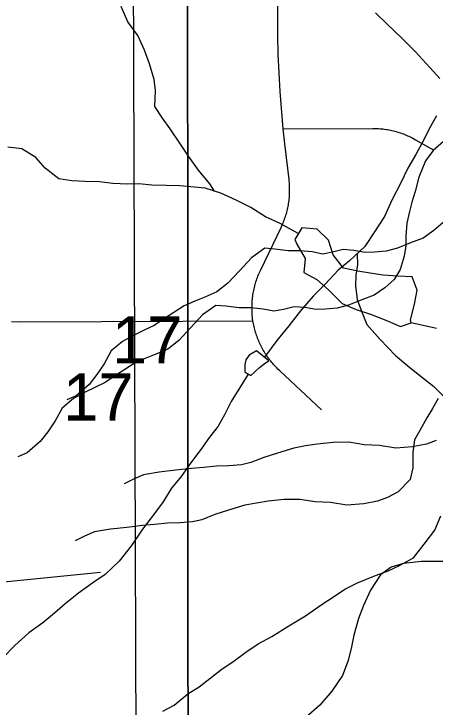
# Model space of a CAD drawing. Extents: x -21.1 to 50.3, y 0 to 22.1.
# Drawn here: x 4.341 to 4.714, y 16.136 to 16.75 of the extents above; entities that cross this region are included whole.
import ezdxf

# ---------------------------------------------------------------- set-up
doc = ezdxf.new("R2010")
doc.units = 0
for name, color, linetype in [('GM_X_Major_River', 7, 'Continuous'), ('GM_X_Minor_Lake', 7, 'Continuous'), ('GM_X_Minor_River', 7, 'Continuous'), ('GM_X_Section', 7, 'Continuous'), ('GM_X_Section_Text', 7, 'Continuous'), ('GM_X_Township_Road', 7, 'Continuous')]:
    doc.layers.add(name, color=color, linetype=linetype)

msp = doc.modelspace()

# ---------------------------------------------------------------- linework, layer by layer
at = {"layer": 'GM_X_Major_River'}
msp.add_lwpolyline([(4.66074, 16.75058), (4.67068, 16.7408), (4.68406, 16.728), (4.69592, 16.71633), (4.70893, 16.70202), (4.71774, 16.69222)], dxfattribs=at)
at = {"layer": 'GM_X_Minor_Lake'}
for points in [[(4.69226, 16.4762), (4.69187, 16.47889), (4.69527, 16.49258), (4.69753, 16.50513), (4.69333, 16.51691), (4.68039, 16.51728), (4.66746, 16.5184), (4.65794, 16.51991), (4.645, 16.52179), (4.63244, 16.52444), (4.62329, 16.53621), (4.61909, 16.54914), (4.60918, 16.55901), (4.59548, 16.56014), (4.58941, 16.54986)], [(4.69225, 16.47623), (4.69187, 16.47889), (4.69527, 16.49258), (4.69753, 16.50513), (4.69333, 16.51691), (4.68039, 16.51728), (4.66746, 16.5184), (4.65794, 16.51991), (4.645, 16.52179), (4.63244, 16.52444), (4.62329, 16.53621), (4.61909, 16.54914), (4.60918, 16.55901), (4.59548, 16.56014), (4.58941, 16.54986)], [(4.58941, 16.54986), (4.59132, 16.54568), (4.59857, 16.53314), (4.59744, 16.5206), (4.60887, 16.51453), (4.61915, 16.50541), (4.63135, 16.49326), (4.64353, 16.48795), (4.65647, 16.48379), (4.6698, 16.47848), (4.68275, 16.47279), (4.69226, 16.4762)], [(4.58941, 16.54986), (4.59132, 16.54568), (4.59857, 16.53314), (4.59744, 16.5206), (4.60887, 16.51453), (4.61915, 16.50541), (4.63135, 16.49326), (4.64353, 16.48795), (4.65647, 16.48379), (4.6698, 16.47848), (4.68275, 16.47279), (4.69225, 16.4762)], [(4.55555, 16.45138), (4.54907, 16.44763), (4.54601, 16.44347), (4.54522, 16.4393), (4.54518, 16.43248), (4.55047, 16.42941), (4.55811, 16.43657), (4.56344, 16.44071), (4.56649, 16.44259)], [(4.56649, 16.44259), (4.55555, 16.45138)]]:
    msp.add_lwpolyline(points, dxfattribs=at)
at = {"layer": 'GM_X_Minor_River'}
for points in [[(4.51842, 16.59266), (4.51438, 16.5992), (4.50409, 16.61135), (4.49532, 16.6235), (4.48769, 16.63528), (4.4793, 16.64782), (4.47243, 16.65731), (4.46557, 16.66757), (4.46631, 16.68164), (4.46515, 16.69152), (4.46095, 16.70521), (4.45636, 16.71737), (4.45064, 16.73028), (4.44187, 16.74244), (4.43576, 16.75612)], [(4.71478, 16.65946), (4.70825, 16.64773), (4.70325, 16.63752), (4.69634, 16.62504), (4.68943, 16.61294), (4.68289, 16.59933), (4.67558, 16.58533), (4.66865, 16.5702), (4.65984, 16.5566), (4.6514, 16.54375), (4.63766, 16.53093), (4.62774, 16.52265), (4.61665, 16.51057), (4.60558, 16.49964), (4.59449, 16.48681), (4.58415, 16.47359), (4.57344, 16.46038), (4.56267, 16.44566)], [(4.72086, 16.63664), (4.71177, 16.62861), (4.70497, 16.61945), (4.69896, 16.60499), (4.69599, 16.59243), (4.69299, 16.58292), (4.69076, 16.57455), (4.68853, 16.56428), (4.68745, 16.55288), (4.6875, 16.54414), (4.68603, 16.53501), (4.68267, 16.52322), (4.67739, 16.51445), (4.66906, 16.50719), (4.65958, 16.50068), (4.64856, 16.49644), (4.63679, 16.49181), (4.62691, 16.4891), (4.61664, 16.48828), (4.60827, 16.48786), (4.59836, 16.4897), (4.58884, 16.49041), (4.57933, 16.48807), (4.57097, 16.48651), (4.56144, 16.48836), (4.55078, 16.48944), (4.54012, 16.48938), (4.52831, 16.49083), (4.51955, 16.49154), (4.5078, 16.48312), (4.49721, 16.47166), (4.48699, 16.46059), (4.47714, 16.45294), (4.46651, 16.44832), (4.45777, 16.44485), (4.44828, 16.44062), (4.43918, 16.43487), (4.43083, 16.42951), (4.42173, 16.42338), (4.413, 16.41915), (4.40275, 16.41415), (4.39365, 16.40917), (4.3838, 16.40075), (4.37739, 16.38932), (4.37097, 16.37979), (4.36417, 16.37101), (4.35281, 16.36107), (4.34445, 16.35761)], [(4.5925, 16.55516), (4.57645, 16.56391), (4.5635, 16.56998), (4.55055, 16.57833), (4.53761, 16.58478), (4.5239, 16.59084), (4.5102, 16.59539), (4.50068, 16.59614), (4.48775, 16.59726), (4.47557, 16.59763), (4.46301, 16.59799), (4.4516, 16.59912), (4.44132, 16.59872), (4.42839, 16.59947), (4.41659, 16.60097), (4.40403, 16.60134), (4.39224, 16.6017), (4.38082, 16.60359), (4.36863, 16.61308), (4.36024, 16.62258), (4.34806, 16.63016), (4.3355, 16.63167)], [(4.72068, 16.56497), (4.71235, 16.55771), (4.70287, 16.5512), (4.69185, 16.54695), (4.68008, 16.54233), (4.6702, 16.53962), (4.65993, 16.5388), (4.65155, 16.53837), (4.64165, 16.54022), (4.63213, 16.54092), (4.62262, 16.53859), (4.61426, 16.53702), (4.60473, 16.53887), (4.59407, 16.53995), (4.58341, 16.53989), (4.5716, 16.54135), (4.56284, 16.54206), (4.55109, 16.53363), (4.5405, 16.52218), (4.53028, 16.51111), (4.52043, 16.50345), (4.5098, 16.49884), (4.50106, 16.49537), (4.49157, 16.49114), (4.48247, 16.48539), (4.47412, 16.48002), (4.46502, 16.47389), (4.45629, 16.46967), (4.44604, 16.46467), (4.43693, 16.45968), (4.42708, 16.45127), (4.42068, 16.43984), (4.41426, 16.4303), (4.40746, 16.42153), (4.39609, 16.41159), (4.38774, 16.40812)], [(4.64441, 16.53722), (4.64485, 16.52785), (4.64327, 16.51838), (4.64321, 16.50889), (4.64464, 16.49674), (4.64837, 16.48647), (4.65323, 16.47468), (4.6649, 16.46133), (4.67847, 16.44721), (4.68942, 16.43804), (4.69999, 16.42963), (4.71245, 16.41969), (4.72413, 16.40785)], [(4.7146, 16.47123), (4.69225, 16.47623)], [(4.54806, 16.4308), (4.53324, 16.40637), (4.52709, 16.39465), (4.52172, 16.38482), (4.51406, 16.375), (4.5064, 16.36404), (4.49721, 16.35196), (4.48879, 16.34025), (4.48037, 16.32968), (4.47232, 16.31683), (4.46236, 16.30361), (4.45471, 16.29341), (4.44512, 16.27906), (4.43403, 16.26509), (4.42181, 16.2534), (4.41075, 16.24588), (4.39817, 16.23685), (4.38635, 16.22744), (4.3768, 16.21915), (4.3665, 16.21049), (4.3543, 16.20183), (4.34171, 16.19053), (4.33139, 16.17997)], [(4.71605, 16.40906), (4.71115, 16.4003), (4.70625, 16.39191), (4.69984, 16.38086), (4.69532, 16.37248), (4.69386, 16.36145), (4.69393, 16.34778), (4.69133, 16.33751), (4.68073, 16.32643), (4.67124, 16.32144), (4.66251, 16.31835), (4.65034, 16.316), (4.6355, 16.31478), (4.62102, 16.31698), (4.60732, 16.31767), (4.59398, 16.31987), (4.5799, 16.31979), (4.56582, 16.31819), (4.55556, 16.31662), (4.54529, 16.31466), (4.53085, 16.3104), (4.51869, 16.30653), (4.5073, 16.30191), (4.49893, 16.29997), (4.4879, 16.29915), (4.47686, 16.2987), (4.46545, 16.2975), (4.4548, 16.29668), (4.44072, 16.29508), (4.42627, 16.29348), (4.4122, 16.29113), (4.40347, 16.28728), (4.39512, 16.28305)], [(4.71453, 16.37196), (4.70579, 16.36887), (4.69363, 16.36652), (4.67879, 16.3653), (4.66431, 16.3675), (4.65061, 16.36818), (4.63727, 16.37039), (4.62319, 16.37031), (4.60911, 16.36871), (4.59885, 16.36713), (4.58858, 16.36518), (4.57414, 16.36092), (4.56198, 16.35705), (4.55059, 16.35243), (4.54222, 16.35048), (4.53119, 16.34966), (4.52015, 16.34922), (4.50874, 16.34802), (4.49809, 16.3472), (4.48401, 16.3456), (4.46956, 16.344), (4.45549, 16.34164), (4.44676, 16.3378), (4.4384, 16.33357)], [(4.47284, 16.13245), (4.4828, 16.13762), (4.49473, 16.14769), (4.5047, 16.154), (4.51431, 16.16145), (4.52508, 16.17003), (4.53467, 16.17596), (4.5462, 16.18452), (4.55695, 16.19195), (4.5692, 16.19861), (4.58416, 16.20788), (4.59874, 16.21677), (4.61371, 16.22718), (4.62368, 16.23349), (4.63367, 16.24055), (4.64477, 16.24608), (4.65929, 16.25194), (4.6719, 16.25669), (4.68147, 16.2611), (4.69449, 16.26812), (4.70379, 16.28013), (4.7131, 16.29253), (4.71862, 16.30536)], [(4.72282, 16.26483), (4.71143, 16.2649), (4.70156, 16.26496), (4.68561, 16.26316), (4.67459, 16.25981), (4.66505, 16.25304), (4.65624, 16.23944), (4.65008, 16.22582), (4.64583, 16.21446), (4.64156, 16.19969), (4.63959, 16.18946), (4.63647, 16.17733), (4.63145, 16.16409), (4.62225, 16.15011), (4.61155, 16.13765), (4.59934, 16.1271)]]:
    msp.add_lwpolyline(points, dxfattribs=at)
at = {"layer": 'GM_X_Section'}
for points in [[(4.44556, 17.13365), (5.45266, 17.13084), (5.44952, 16.13321), (4.44906, 16.1053)], [(5.52017, 16.94387), (5.53343, 15.91957), (5.47621, 15.91802), (4.49511, 15.90479), (4.49436, 16.90218), (4.49435, 16.93023)], [(4.49436, 16.90218), (4.49511, 15.90479), (3.50758, 15.88397), (3.48674, 15.88357), (3.4856, 16.89423)]]:
    msp.add_lwpolyline(points, close=True, dxfattribs=at)
at = {"layer": 'GM_X_Township_Road'}
for points in [[(4.61306, 16.3992), (4.57623, 16.43362), (4.5745, 16.43524), (4.57356, 16.43617), (4.57264, 16.43712), (4.57173, 16.43808), (4.57084, 16.43906), (4.56996, 16.44005), (4.56911, 16.44106), (4.56827, 16.44209), (4.56744, 16.44312), (4.56664, 16.44417), (4.56586, 16.44524), (4.56509, 16.44632), (4.56435, 16.44741), (4.56362, 16.44852), (4.56291, 16.44963), (4.56222, 16.45077), (4.56155, 16.45191), (4.56091, 16.45306), (4.56028, 16.45423), (4.55967, 16.4554), (4.55908, 16.45659), (4.55851, 16.45778), (4.55797, 16.45899), (4.55745, 16.4602), (4.55694, 16.46143), (4.55646, 16.46266), (4.556, 16.4639), (4.55556, 16.46515), (4.55515, 16.46641), (4.55475, 16.46767), (4.55438, 16.46894), (4.55403, 16.47021), (4.5537, 16.4715), (4.55339, 16.47279), (4.55311, 16.47408), (4.55285, 16.47538), (4.55262, 16.47668), (4.55239, 16.47801), (4.55213, 16.47986), (4.55197, 16.48118), (4.55184, 16.48249), (4.55172, 16.48381), (4.55164, 16.48513), (4.55157, 16.48645), (4.55165, 16.49439), (4.55175, 16.49571), (4.55187, 16.49703), (4.552, 16.49834), (4.55217, 16.49965), (4.55236, 16.50097), (4.55256, 16.50227), (4.5528, 16.50358), (4.55305, 16.50487), (4.55333, 16.50617), (4.55363, 16.50745), (4.55395, 16.50874), (4.55429, 16.51002), (4.55466, 16.51129), (4.55505, 16.51255), (4.55546, 16.51381), (4.5559, 16.51506), (4.55635, 16.5163), (4.55683, 16.51754), (4.55733, 16.51876), (4.55784, 16.51998), (4.55838, 16.52119), (4.55895, 16.52239), (4.57755, 16.5612), (4.57829, 16.5628), (4.57882, 16.56401), (4.57933, 16.56523), (4.57982, 16.56646), (4.58029, 16.56769), (4.58073, 16.56894), (4.58116, 16.57019), (4.58156, 16.57145), (4.58194, 16.57272), (4.5823, 16.574), (4.58264, 16.57528), (4.58295, 16.57656), (4.58324, 16.57785), (4.58351, 16.57915), (4.58375, 16.58045), (4.58397, 16.58176), (4.58417, 16.58306), (4.58435, 16.58438), (4.58451, 16.58569), (4.58464, 16.58701), (4.58474, 16.58832), (4.58483, 16.58965), (4.58468, 16.60022), (4.58456, 16.60154), (4.58441, 16.60286), (4.58063, 16.63447), (4.57916, 16.64791), (4.57639, 16.68077), (4.57543, 16.69728), (4.57476, 16.71381), (4.57438, 16.73035), (4.57428, 16.74689), (4.57461, 16.85156)], [(4.57916, 16.64791), (4.65827, 16.64821), (4.66356, 16.64804), (4.66488, 16.64794), (4.6662, 16.64783), (4.66751, 16.64768), (4.66883, 16.64751), (4.67014, 16.64732), (4.67144, 16.64711), (4.67275, 16.64687), (4.67404, 16.64662), (4.67534, 16.64633), (4.67662, 16.64602), (4.6779, 16.6457), (4.67918, 16.64535), (4.68045, 16.64498), (4.68171, 16.64459), (4.68297, 16.64417), (4.68422, 16.64373), (4.68546, 16.64328), (4.6867, 16.64279), (4.68792, 16.64229), (4.68914, 16.64177), (4.69034, 16.64123), (4.69154, 16.64066), (4.69272, 16.64007), (4.6939, 16.63947), (4.6962, 16.6382), (4.71241, 16.62884)], [(4.33892, 16.47738), (4.34638, 16.47699), (4.49046, 16.47758), (4.55239, 16.47801)], [(4.2402, 15.94866), (4.23934, 16.16261), (4.23974, 16.17595), (4.24042, 16.18176), (4.24145, 16.18689), (4.2435, 16.19441), (4.24647, 16.20102), (4.24886, 16.20592), (4.25125, 16.21014), (4.2541, 16.21447), (4.25832, 16.21949), (4.26174, 16.22302), (4.2671, 16.22792), (4.27245, 16.23168), (4.27701, 16.23453), (4.28214, 16.23738), (4.28545, 16.23887), (4.28909, 16.24023), (4.29354, 16.2416), (4.2981, 16.24274), (4.30266, 16.24365), (4.30813, 16.24445), (4.41756, 16.25539)]]:
    msp.add_lwpolyline(points, dxfattribs=at)

# ---------------------------------------------------------------- texts
at = {"layer": 'GM_X_Section_Text'}
for p in [(4.42776, 16.44016), (4.38447, 16.38964)]:
    msp.add_text('17', height=0.041856, rotation=0.00001, dxfattribs=at).set_placement(p)

doc.saveas('drawing.dxf')
